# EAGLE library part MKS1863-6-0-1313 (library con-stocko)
Serie MKS 1850 Lötstifte In-line, Raster 2.5 mm, Stiftwannen, stehend, mit Rastlasche Source: http://www.stocko.de/de/index.php?seite=ka_rfk2_mks1850.html&rubrik=Katalog+-+RFK+2 rfk_1850.pdf
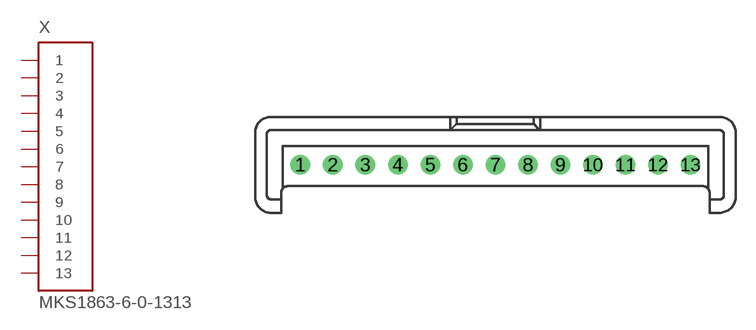
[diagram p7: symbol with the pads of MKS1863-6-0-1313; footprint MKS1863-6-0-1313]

Designator prefix X

## MKS1863-6-0-1313 (OC_FARNELL: unknown; OC_NEWARK: unknown)  [MKS1863-6-0-1313]
1  1  in
2  2  in
3  3  in
4  4  in
5  5  in
6  6  in
7  7  in
8  8  in
9  9  in
10  10  in
11  11  in
12  12  in
13  13  in

## Footprint MKS1863-6-0-1313 (pad centres in mm)
Serie MKS 1850 Lötstifte In-line, Raster 2.5 mm, Stiftwannen, stehend, mit Rastlasche Source: http://www.stocko.de/de/index.php?seite=ka_rfk2_mks1850.html&rubrik=Katalog+-+RFK+2 rfk_1850.pdf
drill 1 pad 1.422 round: 1 -15,0; 2 -12.5,0; 3 -10,0; 4 -7.5,0; 5 -5,0; 6 -2.5,0; 7 0,0; 8 2.5,0; 9 5,0; 10 7.5,0; 11 10,0; 12 12.5,0; 13 15,0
